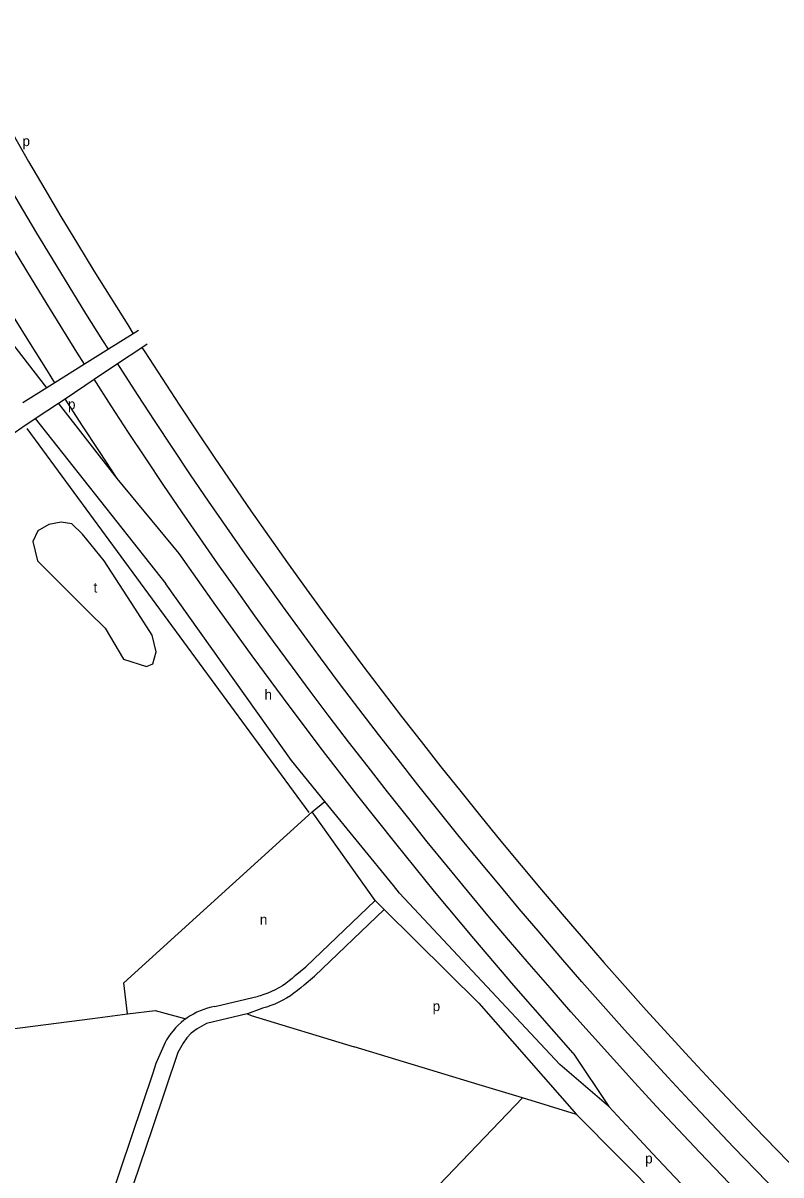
# Model space of a CAD drawing. Extents: x 156066 to 157805, y 383432 to 385631.
# Drawn here: x 156549.2 to 156846.9, y 385173.1 to 385625.7 of the extents above; entities that cross this region are included whole.
import ezdxf

# ---------------------------------------------------------------- set-up
doc = ezdxf.new("R2010")
doc.units = 0
for name, color, linetype in [('BLT_Basislijn', 7, 'Continuous'), ('BLT_Centroide', 7, 'Continuous'), ('BLT_Vlakafsluiter', 7, 'Continuous')]:
    doc.layers.add(name, color=color, linetype=linetype)

msp = doc.modelspace()

# ---------------------------------------------------------------- linework, layer by layer
at = {"layer": 'BLT_Basislijn'}
for p, q in [((156592.53, 385503.58), (156582.77, 385497.49)), ((156594.61, 385504.87), (156592.53, 385503.58)), ((156582.77, 385497.49), (156573.4, 385491.64)), ((156586.35, 385491.88), (156595.91, 385498.27)), ((156595.91, 385498.27), (156598.02, 385499.68)), ((156573.4, 385491.64), (156561.73, 385484.37)), ((156577.15, 385485.73), (156586.35, 385491.88)), ((156561.73, 385484.37), (156558.51, 385482.35)), ((156565.72, 385478.09), (156577.15, 385485.73)), ((156558.51, 385482.35), (156549.12, 385476.5)), ((156554.03, 385470.28), (156563.15, 385476.37)), ((156563.15, 385476.37), (156565.72, 385478.09)), ((156586.13, 385446.8), (156563.15, 385476.37)), ((156554.03, 385470.28), (156605.29, 385405.29)), ((156550.77, 385466.32), (156661.42, 385315.44)), ((156662.71, 385315.74), (156667.75, 385319.85)), ((156694.72, 385286.77), (156667.75, 385319.85)), ((156687.56, 385280.94), (156662.71, 385315.74)), ((156687.56, 385280.94), (156660.26, 385254.84)), ((156691.11, 385277.41), (156663.72, 385251.22)), ((156656.1, 385251.43), (156660.26, 385254.84)), ((156659.58, 385247.83), (156663.72, 385251.22)), ((156624.55, 385239.26), (156641.72, 385243.36)), ((156576.54, 385234.6), (156590.26, 385236.37)), ((156637.24, 385236.41), (156637.41, 385236.34)), ((156642.98, 385238.53), (156637.41, 385236.34)), ((156605.03, 385225.2), (156601.42, 385216.88)), ((156728.36, 385208.5), (156679.22, 385223.46)), ((156601.42, 385216.88), (156600.14, 385213.08)), ((156600.14, 385213.08), (156571.69, 385128.4)), ((156745.33, 385203.34), (156728.36, 385208.5)), ((156700.39, 385156.45), (156745.33, 385203.34)), ((156766.62, 385196.86), (156745.33, 385203.34)), ((156895.07, 385067.48), (156766.62, 385196.86))]:
    msp.add_line(p, q, dxfattribs=at)
for points in [[(156520.96, 385625.69), (156526.82, 385614.9), (156532.87, 385603.94), (156538.98, 385593.02), (156545.16, 385582.14), (156551.41, 385571.29), (156557.73, 385560.48), (156564.11, 385549.72), (156570.56, 385538.99), (156577.08, 385528.3), (156583.67, 385517.66), (156590.32, 385507.05), (156592.53, 385503.58)], [(156582.77, 385497.49), (156580.6, 385500.91), (156573.91, 385511.58), (156567.28, 385522.28), (156560.73, 385533.03), (156554.24, 385543.82), (156547.82, 385554.65), (156541.47, 385565.52), (156535.18, 385576.43), (156528.96, 385587.37), (156522.81, 385598.36), (156516.73, 385609.38), (156511.27, 385619.43)], [(156573.4, 385491.64), (156570.4, 385496.37), (156563.76, 385506.96), (156557.2, 385517.59), (156550.7, 385528.27), (156544.26, 385538.98), (156537.89, 385549.73), (156531.59, 385560.52), (156525.35, 385571.35), (156519.18, 385582.22), (156513.08, 385593.13)], [(156561.73, 385484.37), (156558.77, 385489.04), (156552.09, 385499.7), (156545.48, 385510.4), (156538.93, 385521.15), (156532.45, 385531.94), (156526.04, 385542.76), (156519.69, 385553.62), (156513.41, 385564.53), (156507.2, 385575.47), (156501.06, 385586.45)], [(156558.51, 385482.35), (156537.45, 385509.45), (156525.26, 385521.99)], [(156595.91, 385498.27), (156597.04, 385496.49), (156603.82, 385485.97), (156610.67, 385475.5), (156617.59, 385465.06), (156624.57, 385454.67), (156631.61, 385444.32), (156638.72, 385434.02), (156645.89, 385423.76), (156653.13, 385413.55), (156660.43, 385403.38), (156667.8, 385393.26), (156675.22, 385383.18), (156682.71, 385373.15), (156690.27, 385363.17), (156697.88, 385353.24), (156705.56, 385343.35), (156713.3, 385333.51), (156721.1, 385323.72), (156728.96, 385313.98), (156736.88, 385304.29), (156744.86, 385294.65), (156752.9, 385285.06), (156761.01, 385275.51), (156769.17, 385266.02), (156777.39, 385256.58), (156785.67, 385247.2), (156794.01, 385237.86), (156802.4, 385228.58), (156810.86, 385219.34), (156819.37, 385210.17), (156827.94, 385201.04), (156836.56, 385191.97), (156845.25, 385182.95), (156853.99, 385173.99)], [(156845.78, 385165.94), (156836.99, 385174.95), (156828.26, 385184.02), (156819.58, 385193.14), (156810.96, 385202.32), (156802.4, 385211.55), (156793.9, 385220.84), (156785.45, 385230.17), (156777.07, 385239.56), (156768.74, 385249), (156760.47, 385258.5), (156752.26, 385268.04), (156744.12, 385277.64), (156736.03, 385287.29), (156728, 385296.98), (156720.03, 385306.73), (156712.13, 385316.53), (156704.28, 385326.37), (156696.5, 385336.27), (156688.78, 385346.21), (156681.12, 385356.21), (156673.52, 385366.24), (156665.99, 385376.33), (156658.52, 385386.46), (156651.11, 385396.64), (156643.77, 385406.87), (156636.49, 385417.14), (156629.27, 385427.46), (156622.12, 385437.82), (156615.04, 385448.23), (156608.02, 385458.68), (156601.07, 385469.17), (156594.18, 385479.71), (156587.35, 385490.29), (156586.35, 385491.88)], [(156661.98, 385363.22), (156655.01, 385372.59), (156647.61, 385382.67), (156640.27, 385392.78), (156633, 385402.95), (156625.79, 385413.15), (156618.64, 385423.4), (156611.56, 385433.7), (156604.54, 385444.04), (156597.58, 385454.42), (156590.69, 385464.84), (156583.86, 385475.31), (156577.15, 385485.73)], [(156586.13, 385446.8), (156579.19, 385457.3), (156572.32, 385467.83), (156565.72, 385478.09)], [(156533.1, 385456.96), (156533.5, 385456.34), (156548.77, 385466.76), (156554.03, 385470.28)], [(156765.27, 385220.93), (156742.01, 385247.54), (156726.29, 385265.95), (156710.86, 385284.51), (156695.69, 385303.27), (156680.71, 385322.07), (156665.98, 385341.12), (156651.47, 385360.37), (156639.2, 385377.06), (156624.99, 385396.78), (156610.58, 385417.29), (156586.13, 385446.8)], [(156667.75, 385319.85), (156654.63, 385335.94), (156605.29, 385405.29)], [(156849.91, 385146.05), (156841.11, 385154.93), (156832.37, 385163.86), (156823.68, 385172.84), (156815.04, 385181.87), (156806.47, 385190.96), (156797.94, 385200.1), (156789.48, 385209.29), (156781.07, 385218.54), (156772.72, 385227.84), (156764.42, 385237.18), (156756.19, 385246.58), (156748.01, 385256.03), (156739.89, 385265.53), (156731.83, 385275.08), (156723.83, 385284.68), (156715.89, 385294.33), (156708, 385304.03), (156700.18, 385313.78), (156692.42, 385323.57), (156684.72, 385333.41), (156677.08, 385343.3), (156669.5, 385353.24), (156661.98, 385363.22)], [(156590.26, 385236.37), (156588.75, 385248.63), (156662.71, 385315.74)], [(156779.34, 385200.01), (156760.06, 385216.48), (156697.09, 385283.87), (156694.72, 385286.77)], [(156691.11, 385277.41), (156687.56, 385280.94)], [(156728.2, 385240.62), (156691.11, 385277.41)], [(156656.1, 385251.43), (156654.92, 385250.34), (156653.68, 385249.31), (156652.4, 385248.34), (156651.07, 385247.44), (156649.69, 385246.61), (156648.28, 385245.85), (156646.83, 385245.15), (156645.34, 385244.53), (156643.83, 385243.99), (156642.3, 385243.52), (156641.72, 385243.36)], [(156659.58, 385247.83), (156658.31, 385246.66), (156656.99, 385245.55), (156655.61, 385244.5), (156654.2, 385243.51), (156652.73, 385242.6), (156651.23, 385241.75), (156649.69, 385240.97), (156648.11, 385240.26), (156646.51, 385239.63), (156644.87, 385239.07), (156643.21, 385238.59), (156642.98, 385238.53)], [(156624.55, 385239.26), (156623.1, 385238.96), (156621.66, 385238.58), (156620.24, 385238.13), (156618.85, 385237.6), (156617.49, 385237), (156616.16, 385236.33), (156614.87, 385235.58), (156613.62, 385234.77), (156613.2, 385234.46)], [(156728.2, 385240.62), (156766.62, 385196.86)], [(156590.26, 385236.37), (156601.09, 385237.77), (156613.2, 385234.46)], [(156637.24, 385236.41), (156621.26, 385232.57), (156617.55, 385230.46), (156615.3, 385228.78), (156613.58, 385226.99), (156612.07, 385224.93), (156610.01, 385221.2), (156599.96, 385191.23)], [(156637.41, 385236.34), (156638.84, 385235.71), (156679.22, 385223.46)], [(156397.01, 385215.36), (156403.28, 385212.27), (156576.54, 385234.6)], [(156613.2, 385234.46), (156612.42, 385233.89), (156611.27, 385232.95), (156610.17, 385231.95), (156609.13, 385230.89), (156608.14, 385229.77), (156607.22, 385228.61), (156606.36, 385227.39), (156605.56, 385226.13), (156605.03, 385225.2)], [(156849.1, 385127.46), (156840.18, 385136.34), (156831.32, 385145.28), (156822.52, 385154.26), (156813.77, 385163.31), (156805.07, 385172.4), (156796.44, 385181.55), (156787.86, 385190.76), (156779.34, 385200.01)], [(156599.96, 385191.23), (156580.29, 385133.36), (156566.73, 385094.47)]]:
    msp.add_lwpolyline(points, dxfattribs=at)
msp.add_lwpolyline([(156568.43, 385428.87), (156564.2, 385429.52), (156559.4, 385428.67), (156555.03, 385426.14), (156553.05, 385422.04), (156554.93, 385414.38), (156563.43, 385405.86), (156574.97, 385394.39), (156581.5, 385387.9), (156588.67, 385375.76), (156597.77, 385372.88), (156600.19, 385373.95), (156601.5, 385378.59), (156599.88, 385385.21), (156593.07, 385395.83), (156581.13, 385414.45), (156572.61, 385424.87)], close=True, dxfattribs=at)
at = {"layer": 'BLT_Vlakafsluiter'}
msp.add_line((156765.27, 385220.93), (156779.34, 385200.01), dxfattribs=at)

# ---------------------------------------------------------------- texts
at = {"layer": 'BLT_Centroide'}
for s, p in [('p', (156548.98, 385577.33)), ('p', (156566.85, 385473.93)), ('t', (156576.9, 385401.93)), ('h', (156644.04, 385359.81)), ('n', (156642.2, 385271.44)), ('p', (156710.08, 385237.46)), ('p', (156793.53, 385177.62))]:
    msp.add_text(s, height=4, dxfattribs=at).set_placement(p)

doc.saveas('drawing.dxf')
